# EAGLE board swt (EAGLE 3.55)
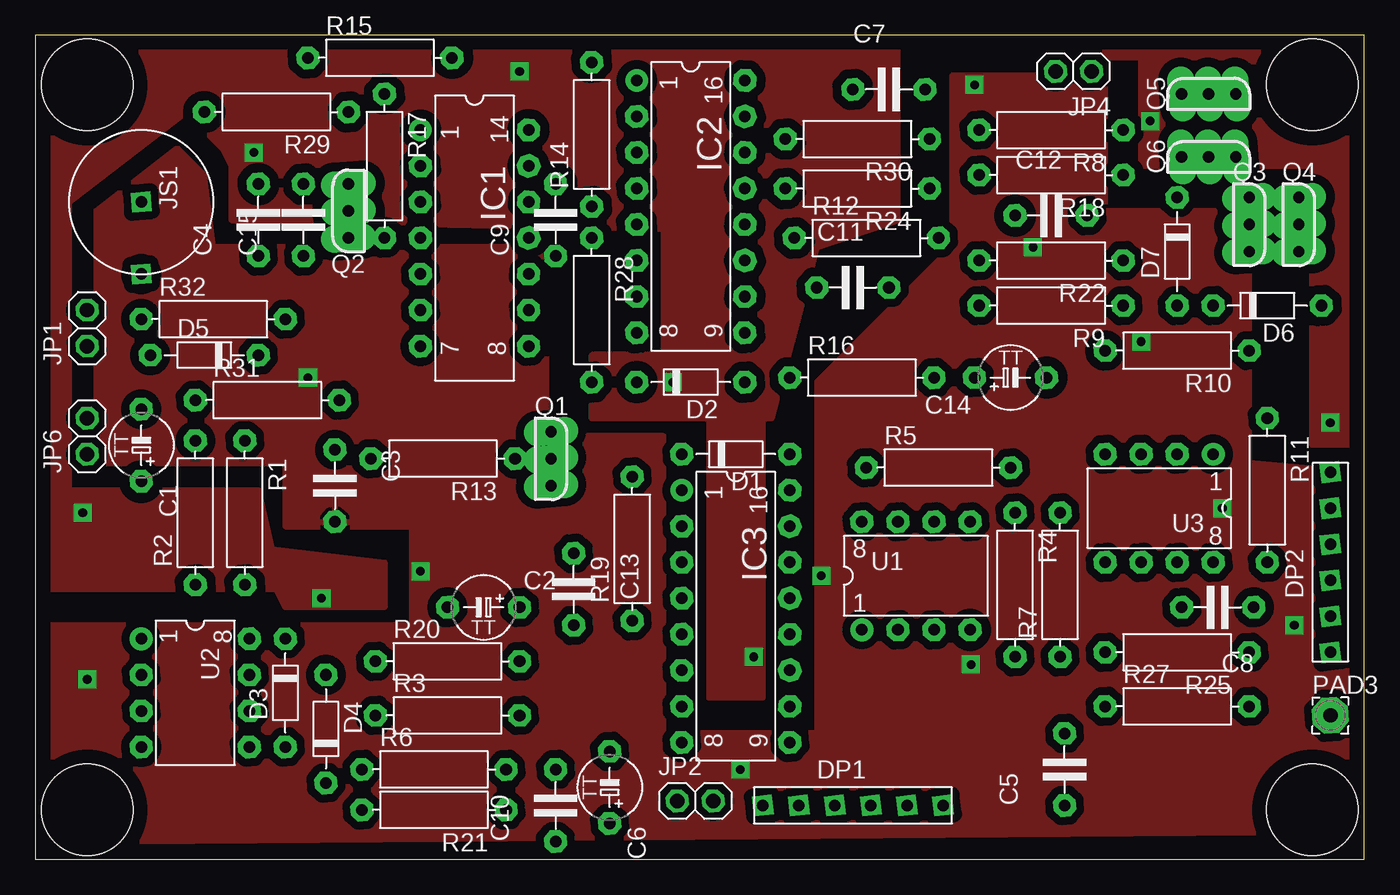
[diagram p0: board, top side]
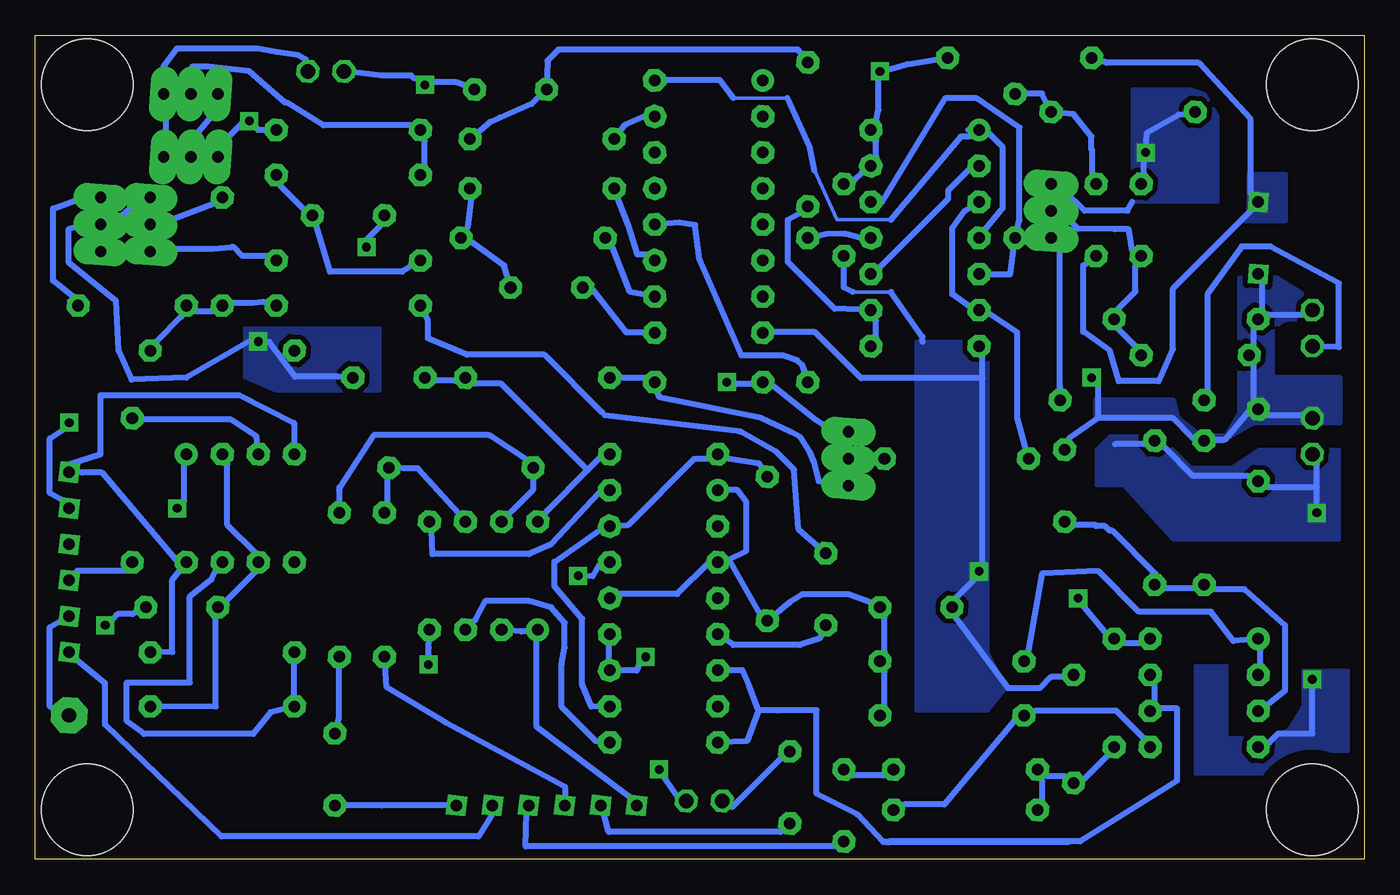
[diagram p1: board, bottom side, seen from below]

Size 93.65 x 58.09 mm. Coordinates in mm from the lower left corner, seen from the top.
Outline: 0,0 93.65,0 93.65,58.09 0,58.09 0,0
Copper layers used: Top, Bottom
Holes 6.45 mm at 3.64,54.61 90,3.49 90,54.61 3.64,3.49
tRestrict: area 21.4,47 to 22.7,48.3; area 80.2,48.9 to 81.4,50.2; area 6.7,26 to 8.2,27.4; area 3,38.1 to 4.3,39.4; area 10.6,28.9 to 11.9,30.2; area 3,30.5 to 4.3,31.7; area 20.5,28.3 to 21.7,29.5; area 26.5,35.6 to 27.8,36.8; area 28.4,17.1 to 29.7,18.4; area 6.8,7.3 to 8.1,8.6; area 82.4,27.9 to 83.7,29.2; area 85.2,17.1 to 86.5,18.4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

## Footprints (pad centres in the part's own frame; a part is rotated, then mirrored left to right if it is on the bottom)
P5-45 = drill 0.813 pad 1.6 octagon:  -2.54,0;  2.54,0
5 = drill 0.813 pad 1.6 octagon:  -2.54,0;  2.54,0
7,5 = drill 0.813 pad 1.6 octagon:  -3.81,0;  3.81,0
DT1 = drill 0.813 pad 1.397 square:  -6.35,0;  -3.81,0;  -1.27,0;  1.27,0;  3.81,0;  6.35,0
L14 = drill 0.813 pad 1.6 round:  -7.62,-3.81 | drill 0.813 pad 1.6 octagon:  -5.08,-3.81;  -2.54,-3.81;  0,-3.81;  2.54,-3.81;  5.08,-3.81;  7.62,-3.81;  7.62,3.81;  5.08,3.81;  2.54,3.81;  0,3.81;  -2.54,3.81;  -5.08,3.81;  -7.62,3.81
L16 = drill 0.813 pad 1.6 round:  -8.89,-3.81 | drill 0.813 pad 1.6 octagon:  -6.35,-3.81;  -3.81,-3.81;  -1.27,-3.81;  1.27,-3.81;  3.81,-3.81;  6.35,-3.81;  8.89,-3.81;  8.89,3.81;  6.35,3.81;  3.81,3.81;  1.27,3.81;  -1.27,3.81;  -3.81,3.81;  -6.35,3.81;  -8.89,3.81
02 = drill 1.016 pad 1.6 octagon:  -1.27,0;  1.27,0
T1 = drill 0.813 pad 1.397 square:  5.08,0;  0,0
54/1,0 = drill 1.016 pad 2.54 octagon:  0,0
LINE = drill 0.8 pad 1.93 long:  0,-1.905;  0,0;  0,1.905
10 = drill 0.813 pad 1.6 octagon:  -5.08,0;  5.08,0
L08 = drill 0.813 pad 1.6 round:  -3.81,-3.81 | drill 0.813 pad 1.6 octagon:  -1.27,-3.81;  1.27,-3.81;  3.81,-3.81;  3.81,3.81;  1.27,3.81;  -1.27,3.81;  -3.81,3.81

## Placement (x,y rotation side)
C1  10u  [P5-45]  7.46,29.2 270 top
C2  2u2  [P5-45]  31.58,17.77 0 top
C3  100n  [5]  21.11,26.35 270 top
C4  220n  [5]  15.71,45.08 90 top
C5  2u2  [5]  72.54,6.34 90 top
C6  2u2  [P5-45]  40.48,5.08 270 top
C7  2n2  [5]  60.16,54.29 0 top
C8  2n2  [5]  83.34,17.77 180 top
C9  100n  [5]  36.66,45.08 90 top
C10  100N  [5]  36.66,3.8 90 top
C11  10n  [5]  57.62,40.32 0 top
C12  100n  [5]  71.59,45.4 0 top
C13  33n  [5]  37.94,19.04 270 top
C14  10u  [P5-45]  68.73,33.97 180 top
C15  2n2  [5]  18.88,45.08 90 top
D1  1N4148  [7,5]  49.37,28.57 180 top
D2  1N4148  [7,5]  46.19,33.65 180 top
D3  1N4148  [7,5]  17.61,11.74 90 top
D4  1N4148  [7,5]  20.47,9.2 270 top
D5  1N4148  [7,5]  11.9,35.55 0 top
D6  BAT85  [7,5]  86.83,39.05 180 top
D7  BAT85  [7,5]  80.48,42.86 90 top
DP1  Talk  [DT1]  57.62,3.8 0 top
DP2  Call  [DT1]  91.28,20.95 90 top
IC1  4011  [L14]  30.95,43.81 270 top
IC2  4060  [L16]  46.19,46.03 270 top
IC3  DG403  [L16]  49.37,17.14 270 top
JP1  LED  [02]  3.64,37.46 90 top
JP2  Spk/Mic  [02]  46.51,4.12 0 top
JP4  Buzzer  [02]  73.18,55.56 180 top
JP6  Batt  [02]  3.64,29.84 90 top
JS1  Jitter Switch  [T1]  7.46,46.35 270 top
PAD3  LINE  [54/1,0]  91.28,10.16 0 top
Q1  ZTX214  [LINE]  36.35,28.25 0 top
Q2  ZTX109  [LINE]  22.06,45.72 180 top
Q3  ZTX109  [LINE]  85.56,44.76 0 top
Q4  ZTX109  [LINE]  89.05,44.76 0 top
Q5  ZTX214  [LINE]  82.7,53.97 90 top
Q6  ZTX214  [LINE]  82.7,49.53 90 top
R1  2M2  [10]  14.76,24.44 270 top
R2  2M2  [10]  11.27,24.44 90 top
R3  10M  [10]  29.04,10.16 0 top
R4  4K7  [10]  69.05,19.36 270 top
R5  1M  [10]  63.65,27.62 0 top
R6  10K  [10]  28.09,6.34 0 top
R7  620R  [10]  72.22,19.36 90 top
R8  2M2  [10]  71.59,51.43 180 top
R9  62K  [10]  71.59,39.05 180 top
R10  2M2  [10]  80.48,35.87 180 top
R11  620R  [10]  86.83,26.03 270 top
R12  2M2  [10]  58.57,43.81 0 top
R13  62K  [10]  28.73,28.25 180 top
R14  10K  [10]  39.2,51.11 90 top
R15  510K  [10]  24.28,56.51 0 top
R16  27R  [10]  58.25,33.97 0 top
R17  10K  [10]  24.6,48.89 270 top
R18  100K  [10]  71.59,48.26 180 top
R19  1M  [10]  42.06,21.9 90 top
R20  390R  [10]  29.04,13.97 0 top
R21  2K2  [10]  28.09,3.49 180 top
R22  1K  [10]  71.59,42.22 180 top
R24  1M  [10]  57.94,47.3 180 top
R25  150K  [10]  80.48,14.6 180 top
R27  150K  [10]  80.48,10.79 0 top
R28  1M  [10]  39.2,38.73 270 top
R29  510K  [10]  16.98,52.7 180 top
R30  1M  [10]  57.94,50.8 180 top
R31  10K  [10]  16.34,32.38 0 top
R32  4M7  [10]  12.54,38.1 0 top
U1  LM358N  [L08]  62.06,20 0 top
U2  OP296GP  [L08]  11.27,11.74 270 top
U3  7555  [L08]  79.21,24.76 180 top

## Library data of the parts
C1 C2 C6 C14 = cap-tant
C3-C5 C7-C13 C15 D1-D7 R1-R22 R24 R25 R27-R32 = discrete
DP1 DP2 JS1 = pete
IC1 IC2 = 40xx
IC3 = dil
JP1 JP2 JP4 JP6 = pinhead
PAD3 = wirepad
Q1-Q6 = zetex
U1-U3 = linear

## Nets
0V: C2. IC3. R3. R19. R20.
GND: C1. C2. C3. C7. C8. C9. C12. C14. D4. D5. IC1. IC2. IC3. JP1. JP2. JP4. JP6. JS1. Q3. Q4. R2. R10. R32. U1. U2. U3.
N$1: R4. R5. U1.
N$2: D1. IC3. R19.
N$3: D6. D7. R9. R10.
N$4: C5. DP1.
N$5: IC3. U1.
N$6: DP1. R4.
N$7: C3. R1. R2. U2.
N$8: R5. R7. U1.
N$9: C12. R18. R22.
N$10: Q2. R31.
N$11: C6. DP1.
N$12: C13. R9.
N$13: C6. JP2.
N$14: Q1. R13.
N$15: DP1. U1.
N$16: C14. D1. R16. U1.
N$17: R3. R21. U2.
N$18: DP2. R11.
N$19: IC3. U1.
N$20: IC1.
N$21: IC1. R13.
N$22: D6. Q4.
N$23: C5. R7.
N$24: Q3. Q4. R22.
N$25: D2. Q1. R16.
N$26: JP4. Q5. Q6.
N$27: C10. DP1.
N$28: DP2. R25. U3.
N$29: IC2. R12.
N$30: DP2. PAD3.
N$31: IC1. IC2.
N$33: C10. R6.
N$34: C13. IC3.
N$36: C11. IC2.
N$37: D7. Q3.
N$38: R20. U2.
N$39: C11. R12. R24.
N$40: IC3. U2.
N$41: C15. R17. R29.
N$42: IC2. R30.
N$43: IC1. R17.
N$44: IC2. R24.
N$45: IC1. R14.
N$46: IC2. R28.
N$47: C8. R27. U3.
N$48: R25. R27. U3.
N$49: R11. U3.
N$51: C7. R14. R30.
N$52: IC1. R28.
N$53: D3. D4. R6. R21.
N$54: C4. D5. Q2. R32.
N$55: JP1. R31.
N$56: Q5. Q6.
N$57: C15. JS1. R15.
N$58: Q5. R8. R18.
RECEIVE: DP1. DP2.
V+: C1. C4. C9. D2. D3. DP2. IC1. IC3. JP6. Q1. Q2. Q6. R1. R8. R15. R29. U2.

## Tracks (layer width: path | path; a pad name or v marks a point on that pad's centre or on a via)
0V
  Bottom 0.406: 53.17,18.41 52.49,18.71 48.42,18.71 46.19,20.95 45.55,20.95 44.77,21.15 | 44.77,21.15 43.55,21.76 43.55,25.22 44.16,26.03 45.55,26.03 | 44.77,21.15 42.67,17.47 42.06,16.82 40.5,18.11 39.6,18.69 36.35,18.69 34.81,18.11 C2. 33.8,17.09 33.8,14.65 R20. 33.8,13.23 33.8,10.79 R3.
GND  (via drill 0.61 pad 1.27)
  Bottom 0.254: 7.18,38.83 7.46,38.1 7.79,37.41 | 8.09,35.55 7.79,36.19 | 7.46,31.74 7.79,32.53 | 53.17,20.95 53.91,20.75 | 3.64,8.89 | v27.14,20.31 26.68,19.93 | v27.14,20.31 27.5,19.93 | 18.73,34.16 v19.2,33.97 | v27.14,20.31 26.89,20.75 | R2. 12.05,29.69 | 27.29,19.93 v27.14,20.31 | v77.94,36.51 78.3,36.69 | 88.25,16.89 v88.73,16.5 | 67.01,55.1 67.17,55.26 | 33.34,40.01 36.04,40.01
  Bottom 0.406: 7.18,38.83 7.18,40.66 7.46,41.27 | 7.79,36.19 7.79,37.41 | JP1. 4.33,38.43 6.77,38.43 7.46,38.1 | 7.79,32.53 7.79,34.77 8.09,35.55 | JP6. 4.33,31.31 6.77,31.31 7.46,31.74 8.19,31.52 9.82,29.57 10.63,29.57 R2. | 53.71,20.54 53.17,20.95 | 65.88,16.19 65.93,14.94 65.93,14.36 v65.95,13.74 | 53.91,20.75 54.38,19.96 v55.4,20 | v3.64,12.7 3.64,8.89 6.03,8.89 6.66,8.25 7.46,7.93 | 18.73,31.11 20.79,29.69 21.11,28.89 | 18.73,31.11 18.73,34.16 | 26.89,20.75 26.89,33.93 | 26.89,33.93 26.89,35.58 27.14,36.19 | 26.89,33.93 35.45,33.93 38.7,37.18 41.72,37.18 42.38,37.14 | 12.05,29.69 13.48,31.11 18.73,31.11 | JP2. 48.42,4.49 49.21,5.6 v49.68,6.34 | 27.29,19.93 28.71,18.51 29.04,17.77 28.74,16.99 25.08,12.06 22.86,12.06 22.07,12.86 21.11,12.86 20.47,13.01 | 71.27,33.97 72.31,34.04 75.36,34.04 77.16,36.48 v77.94,36.51 | 78.3,36.69 83.02,33.97 86.88,33.83 87.78,35.87 87.97,39.38 91.3,42.08 91.3,44.46 90.03,44.78 89.87,44.78 89.05,44.76 88.13,44.94 86.22,46.52 Q3. | 83.02,28.57 83.17,27.86 83.17,25.22 v83.66,24.76 | 88.25,16.89 87.85,17.29 86.83,17.29 85.88,17.77 | C7. 63.99,54.78 65.74,54.78 v66.19,54.61 67.01,55.1 | 67.17,55.26 69.23,55.26 JP4. | v27.14,20.31 26.83,19.84 | 33.34,40.01 31.12,36.84 31.12,36.51 | 36.04,40.01 36.68,40.33 36.68,41.76 36.66,42.54 | 69.05,45.4 69.39,44.62 70.34,43.66 v70.32,43.18
  pour Top (isolate 0.559): 10,50.16 4.28,45.72 4.28,27.93 17.61,27.93 17.61,23.49 26.5,23.49 26.5,16.5 1.1,16.5 1.1,6.34 6.82,1.27 86.19,1.9 92.55,6.98 92.55,27.3 85.56,27.93 85.56,45.72 75.4,45.72 75.4,55.24 64.61,55.24 64.61,43.18 55.08,33.65 55.08,8.89 44.28,8.89 44.28,29.84 36.03,29.84 36.03,43.18 12.54,43.18 11.9,48.26
  pour Bottom (isolate 0.356, no thermals): 7.14,41.59 3.01,39.05 3.01,38.1 5.55,38.1 6.5,37.46 6.5,33.97 1.74,33.97 1.74,30.79 7.77,30.79 10,29.52 11.9,29.52 13.49,31.11 18.88,31.11 18.88,32.38 13.49,32.38 13.17,31.11 11.58,29.84 9.68,29.84 8.73,31.43 8.73,40.95
  pour Bottom (isolate 0.356, no thermals): 4.28,13.33 1.1,13.33 1.1,7.62 4.6,7.62 7.14,6.03 11.9,6.03 11.9,13.65 9.68,13.65 9.68,8.57 6.5,8.57 5.23,9.2 4.28,10.79
  pour Bottom (isolate 0.356, no thermals): 26.5,36.51 26.5,14.6 25.23,12.06 26.5,10.47 31.58,10.47 31.58,36.51
  pour Bottom (isolate 0.356, no thermals): 78.89,37.46 78.89,33.97 76.67,33.02 69.37,33.02 69.37,37.46
N$1
  Bottom 0.406: 63.34,23.81 63.46,24 66.71,27.57 67.73,27.57 R5. 68.86,26.84 68.86,25.22 69.05,24.44
N$2
  Bottom 0.254: D1. 44.77,28.27
  Bottom 0.406: D1. 46.19,28.27 47.18,28.27 51.85,23.59 53.17,23.49 53.91,23.18 57.07,20.97 57.07,19.26 55.1,16.97 55.1,12.37 54.46,10.77 53.17,10.79 | 44.77,28.27 42.67,27.95 R19.
N$3
  Bottom 0.406: 76.67,39.05 77.6,39.3 78.3,39.24 79.72,39.24 80.48,39.05 81.14,38.63 82.36,38.63 D6. 83.36,38.27 85.11,36.52 85.56,35.87
N$4
  Bottom 0.406: 64.48,3.48 DP1. 64.62,3.81 69.23,3.81 72.54,3.8
N$5
  Bottom 0.406: 53.17,8.25 54.14,8.33 56.55,10.74 56.55,13.76 56.35,14.92 56.35,16.68 57.3,17.77 58.84,18.22 61.95,18.22 62.65,16.89 63.34,16.19
N$6
  Bottom 0.406: 56.35,3.8 56.32,5.13 64.71,9.63 68.89,12.14 R4.
N$7
  Bottom 0.254: 7.46,10.47 7.14,10.64
  Bottom 0.406: C3. 20.38,23.59 18.96,23.59 18.89,23.5 18.26,23.5 17.94,23.18 17.74,23.18 14.69,20.14 R1. 14.08,19.12 12.05,19.12 11.27,19.36 10.47,19.05 8.41,19.05 5.55,16.51 5.55,11.91 7.14,10.64
N$8
  Bottom 0.406: 60.8,23.81 60.01,24.61 58.59,26.03 58.59,26.84 58.57,27.62 58.99,28.18 61.68,29.92 69.81,29.92 72.22,26.23 72.25,26.04 72.25,25.08 R7.
N$9
  Bottom 0.406: R22. 67.8,41.44 72.88,41.44 73.84,44.62 C12. 74.63,45.73 76.38,47.48 76.67,48.26
N$10
  Bottom 0.254: 21.4,33.14 21.43,33.18
  Bottom 0.406: R31. 21.4,33.14 21.43,33.34 21.43,43.35 Q2.
N$11
  Bottom 0.406: 53.81,3.8 53.62,3.27 53.24,1.94 41.11,1.94 C6.
N$12
  Bottom 0.254: 53.64,31.45 53.71,31.52 53.5,31.31
  Bottom 0.406: 53.71,31.52 57.77,35.58 63.26,35.58 65.99,36.72 65.99,37.94 R9. | 53.5,31.31 43.97,30.16 41.47,28.77 40.17,27.48 39.85,23.27 37.94,21.58
N$13
  Bottom 0.406: 40.48,7.62 41.11,7.13 44.56,3.68 45.24,4.12
N$14
  Bottom 0.406: 33.81,28.25 34.45,28.1 35.41,28.1 36.35,28.25
N$15
  Bottom 0.406: 60.8,16.19 59.4,16.07 58.38,16.07 58.25,16.19 58.32,15.46 58.32,9.34 51.88,4.49 51.27,3.8
N$16
  Bottom 0.406: C14. 65.49,33.75 64.07,33.75 R16. 62.65,33.55 60.82,33.55 54.72,27.45 | 54.72,27.45 57.57,24.61 U1. | 54.72,27.45 53.91,28.27 53.17,28.57
N$17
  Bottom 0.406: 33.17,3.49 32.44,3.88 29.59,3.88 24.65,9.77 23.96,10.16 23.18,10.48 17.46,10.48 15.56,8.57 15.08,7.93
N$18
  Bottom 0.406: 91.28,19.68 90.69,20.34 87.24,20.34 R11.
N$19
  Bottom 0.406: IC3. 53.91,25.83 57.3,22.22 58.84,21.53 65.66,21.53 65.72,23.18 65.88,23.81
N$20
  Bottom 0.406: 34.76,41.27 34.2,41.68 29.32,46.55 29.32,47.16 27.9,48.59 27.14,48.89
N$21
  Bottom 0.254: 24.45,37.15
  Bottom 0.406: 27.14,46.35 28.13,45.74 29.03,44.52 29.03,39.85 27.9,39.04 27.14,38.73 26.35,38.42 24.45,37.15 24.45,31.12 R13.
N$22
  Bottom 0.406: 90.99,39.7 | 90.99,39.7 92.41,40.81 92.41,45.89 89.94,46.81 | 89.94,46.81 89.87,46.84 | 90.64,39.05 90.99,39.7 | Q4. 89.87,46.68 89.94,46.81
N$23
  Bottom 0.406: C5. 72.25,10 72.25,10.48 72.25,11.43 72.25,13.49 72.22,14.28
N$24
  Bottom 0.406: 89.05,42.86 88.13,42.71 86.38,42.71 85.56,42.86 84.63,43.03 84.32,43.03 84.16,43.03 81.14,43.03 79.9,43.14 79.71,43.19 79.08,42.55 77.33,42.55 76.67,42.22
  pour Bottom (isolate 0.356, no thermals): 86.83,42.86 86.83,41.91 83.66,41.91 83.66,42.86
N$25
  Bottom 0.406: 53.17,33.97 52.69,33.93 50.66,33.93 50,33.65 49.64,32.57 42.47,31.11 40.44,30.16 39.74,29.78 39.06,28.74 38.74,27.94 38.42,26.67 37.79,26.36 36.35,26.35
N$26
  Bottom 0.406: 74.45,55.56 74.6,56.4 75.15,56.71 76.62,56.92 77.96,57.16 83.68,57.16 84.63,55.89 84.63,55.73 84.63,54.78 84.61,53.97 84.47,53.03 84.47,50.97 84.61,49.53
  pour Bottom (isolate 0.356, no thermals): 84.61,55.88 85.56,55.88 85.56,52.38 84.61,52.38
N$27
  Bottom 0.406: 58.89,3.8 59.02,3.27 59.09,0.92 37.13,0.92 36.66,1.27
N$28
  Bottom 0.254: 85.58,14.62 85.56,14.6
  Bottom 0.406: 85.58,14.62 84.01,14.61 84.01,19.7 U3. 83.78,21.15 88.95,27.27 90.37,27.27 DP2. 91.39,27.86 89.05,28.57 89.05,32.74 79.29,32.74 75.42,30.78 75.4,28.57
N$29
  Bottom 0.406: 50,39.68 51.73,40 52.98,43.16 53.49,43.81
N$30
  Bottom 0.406: 91.28,17.14 91.91,16.8 92.63,16.39 92.63,10.79 PAD3.
N$31
  Bottom 0.254: IC2. 49.24,55.06 | 40.65,53.67 44.46,53.67 | 38.74,48.59 37.15,45.09 33.34,45.09
  Bottom 0.406: 27.14,43.81 26.89,44.2 25.46,45.94 25.46,50.21 26.48,51.23 27.14,51.43 | 27.14,51.43 27.9,51.43 | 33.34,45.09 28.42,50.97 27.78,50.97 27.14,51.43 | 44.46,53.67 45.41,54.94 49.22,54.94 IC2. | 40.65,53.67 39.06,50.18 38.74,48.59
N$33
  Bottom 0.406: R6. 33.86,5.91 36.03,5.91 C10.
N$34
  Bottom 0.406: C13. 38.35,15.59 39.78,15.12 44.45,15.12 45.55,15.87
N$36
  Bottom 0.406: 50,37.14 51.3,37.16 51.99,37.16 54.32,40.11 55.08,40.32
N$37
  Bottom 0.406: D7. 81.14,46.21 84.48,44.94 84.63,44.94 85.56,44.76
N$38
  Bottom 0.254: 23.65,14.76 23.96,13.97
  Bottom 0.406: 7.46,13.01 7.3,13.81 7.3,14.76 7.46,15.55 9.2,15.4 10.79,17.46 15.87,17.46 18.73,20.32 22.7,20.16 23.65,14.76
N$39
  Bottom 0.406: C11. 60.62,41.88 62.85,43.48 R12. 63.17,44.59 62.85,47.23 63.02,47.3
N$40
  Bottom 0.254: 33.39,1.12 20.79,1.12 | 33.39,1.12 33.49,1.12 | 33.39,1.12 33.53,1.18 33.5,1.27
  Bottom 0.406: 42.69,10.5 43.5,8.33 45.55,8.25 | 42.69,10.5 43.32,12.21 43.81,13.34 45.55,13.33 | 42.69,10.5 41.31,10.5 38.58,10.51 38.58,4.64 35.71,3.17 33.91,1.24 33.71,1.24 33.53,1.18 | 15.08,13.01 14.76,12.22 14.76,11.27 15.08,10.47 14.76,10.63 13.17,10.63 13.17,5.55 20,1.27 33.5,1.27
N$41
  Bottom 0.254: 19.16,50.01 19.21,50.02
  Bottom 0.406: 19.16,50.01 19.16,48.38 C15. | 24.6,53.97 23.81,53.99 22.7,53.99 22.06,52.7 20.48,52.56 19.21,50.97 19.21,50.02
N$42
  Bottom 0.406: 50,52.38 50.66,52.42 52.08,51.79 R30.
N$43
  Bottom 0.406: 27.14,41.27 26.36,41.25 24.94,41.25 R17. 24.29,45.09 24.29,51.61 27.31,53.67 29.53,53.67 33.98,46.36 34.76,46.35
N$44
  Bottom 0.406: 50,42.22 50.25,42.64 51.22,42.65 51.85,44.69 R24.
N$45
  Bottom 0.406: 34.76,36.19 34.4,36.8 34.4,38.02 34.76,38.73 37.32,38.83 40.62,42.12 40.62,45.11 39.19,45.89 39.2,46.03
N$46
  Bottom 0.406: 50,44.76 48.29,44.9 47.16,44.72 46.84,42.29 43.89,35.53 40.95,35.53 39.95,35.17 39.6,34.86 R28.
N$47
  Bottom 0.406: R27. 80.94,10.77 80.94,17.09 C8. 80.33,18.11 78.09,20.34 77.94,20.95 78.09,21.56 80.12,23.59 80.12,27.86 80.48,28.57
N$48
  Bottom 0.406: R25. 75.42,13.84 75.42,11.4 75.4,10.79 77.08,10.38 78.3,8.85 85.99,8.85 87.21,9.75 87.21,12.47 82.77,12.47 82.77,18.54 81.25,19.73 80.94,20.34 80.48,20.95
N$49
  Bottom 0.406: 77.94,28.57 78.07,29.83 79.9,31.02 86.22,31.02 86.83,31.11
N$51
  Bottom 0.406: 63.02,50.8 61.61,51.99 60.91,52.31 58.67,53.27 57.62,54.29 57.57,56.31 56.78,57.09 39.92,57.09 R14.
N$52
  Bottom 0.406: 34.76,43.81 35.42,43.8 36.61,44.12 37.86,44.09 39.2,43.81
N$53
  Bottom 0.406: 17.61,7.93 18.1,7.3 19.68,5.71 D4. 21.11,5.87 22.38,5.87 23.01,6.34 22.7,5.55 22.7,4.28 R21.
N$54
  Bottom 0.406: D5. 16.12,36.19 17.34,37.41 R32. 17.34,38.83 16.12,40.05 16.12,41.88 15.71,42.54 16.32,42.9 16.59,44.43 17.58,44.43 20.16,44.46 21.27,45.57 21.43,45.57 22.06,45.72
N$55
  Bottom 0.406: 3.64,36.19 3.32,36.16 1.78,36.11 1.78,40.62 6.59,43.21 8.62,43.21 11.04,39.85 11.04,33.14 11.27,32.38
N$56
  Bottom 0.406: 82.7,49.53 82.41,50.97 80.98,52.72 80.98,53.03 Q5.
N$57
  Bottom 0.406: 18.88,42.54 19.8,41.88 19.8,37.21 17.93,35.87 17.3,33.73 14.46,33.73 13.48,35.99 13.48,40.25 7.99,45.74 JS1. 7.99,46.96 7.99,52.18 11.66,56.17 18.14,56.17 19.2,56.51
  pour Bottom (isolate 0.356, no thermals): 8.41,45.08 5.55,45.08 5.55,48.26 7.77,48.26 8.09,48.26 8.09,45.72
N$58
  Bottom 0.406: 82.7,53.97 82.57,54.78 82.57,55.89 82.41,55.89 81.46,55.89 78.6,55.58 76.06,53.35 75.9,53.35 73.36,51.76 67.17,51.76 R8. 66.21,50.65 66.21,48.91 R18.
RECEIVE
  Bottom 0.406: 61.43,3.8 61.41,3.27 62.42,1.62 80.53,1.62 88.75,9.52 88.75,12.42 90.69,14.04 91.28,14.6
V+  (via drill 0.61 pad 1.27)
  Bottom 0.254: v3.33,24.44 3.32,24.81 | 51.07,14.24 v50.63,14.28 51.07,13.84 | v34.12,55.56 33.94,55.58 | D3. 18.26,16.03 | 19.84,17.94 v20.15,18.41 | 44.3,33.5 v44.92,33.65
  Bottom 0.406: 34.4,50.65 34.4,49.6 34.76,48.89 35.41,48.43 35.88,47.95 C9. | 34.4,50.65 34.4,50.82 | 3.32,24.81 3.32,26.23 | 3.32,26.23 3.32,27.86 | 3.32,26.23 6.77,26.23 C1. 8.19,27.05 12.05,27.05 14.08,29.08 14.76,29.52 15.51,29.28 17.54,29.28 | 15.51,48.38 15.51,49.14 v15.39,49.84 15.3,51.23 13.07,52.51 R29. | 91.28,24.76 91.91,25.42 92.63,25.83 92.63,29.69 91.71,30.3 v91.28,30.79 | 53.17,15.87 53.21,15.26 53.21,14.04 53.17,13.33 52.49,13.32 51.27,13.32 51.07,13.84 | 33.94,55.58 32.17,56.08 R15. | v34.12,55.56 34.23,55.09 34.23,52.85 34.4,52.04 34.29,51.92 IC1. 34.45,50.65 34.4,50.65 | U2. 15.87,15.24 16.83,15.24 D3. | 18.26,16.03 19.84,17.94 | 44.3,33.5 43.03,33.5 D2. 41.6,33.34 38.58,30.96 38.11,30.64 37.63,30.33 37.31,30.33 Q1. | Q6. 80.35,50.81 80.19,50.81 79.08,51.92 v78.58,52.07 77.96,51.45 77.33,51.45 76.67,51.43 | 22.06,47.62 21.75,47.48 21.11,47.16 19.68,45.73 16.67,45.73 16.34,46.35
  pour Top (isolate 0.635): 60.48,57.46 87.15,57.46 92.55,51.43 92.55,29.2 90,29.2 90,48.89 77.94,48.89 77.94,56.51 60.8,56.51
  pour Top (isolate 0.635): 6.18,57.46 1.1,51.75 1.1,26.03 2.38,26.03 2.38,46.35 10.63,52.7 13.17,50.16 13.81,48.89 13.81,45.08 44.28,44.45 44.28,35.55 39.2,35.55 39.2,31.11 47.46,31.11 47.46,11.43 51.27,11.43 51.27,31.11 51.91,31.11 55.08,43.18 60.8,45.08 60.8,57.46
  pour Top (isolate 0.635): 1.1,26.03 15.71,26.03 16.66,21.9 24.6,20.95 24.6,17.77 17.61,17.77 16.98,19.04 1.1,19.04
  pour Bottom (isolate 0.356, no thermals): 1.74,28.89 7.46,28.89 9.36,27.62 12.22,27.62 14.44,29.84 17.93,29.84 18.88,28.89 18.88,26.35 16.98,26.35 13.49,22.54 1.74,22.54
  pour Bottom (isolate 0.356, no thermals): 11.27,53.97 10.31,52.38 10.31,46.35 16.34,46.35 16.34,54.29 12.22,54.29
